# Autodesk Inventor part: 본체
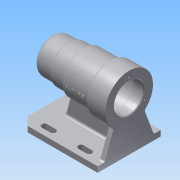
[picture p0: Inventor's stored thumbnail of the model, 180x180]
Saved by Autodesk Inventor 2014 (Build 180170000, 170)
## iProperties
Created: 2017-09
Part Number: 본체
Material: 알루미늄 6061
Document SubType Name: Modeling
Designer: net
Density: 2.71 g/cm^3
Appearance: 알루미늄 - 평지
Mass: 694.456 g
Surface Area: 712.516 cm^2
Volume: 256.257 cm^3
Author: net
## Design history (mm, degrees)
sketch "스케치1"
  geometry: L1 (56, 0)-(-56, 0); L2 (56, 0)-(56, 25); L3 (56, 25)-(31, 25); L4 (31, 25)-(31, 27); L5 (31, 27)-(11, 27); L6 (11, 27)-(11, 30); L7 (11, 30)-(-28, 30); L8 (-28, 30)-(-28, 34); L9 (-28, 34)-(-56, 34); L10 (-56, 21)-(-41, 21); L11 (-41, 21)-(-41, 21); L12 (-38, 24)-(10, 24); L13 (13, 21)-(13, 21); L14 (13, 21)-(24.7, 21); L15 (25, 20.7)-(25, 17.5); L16 (25, 17.5)-(42.7, 17.5); L17 (43, 17.2)-(43, 16); L18 (43, 16)-(46.7, 16); L19 (47, 15.7)-(47, 10.5); L20 (47, 10.5)-(47, 10.5); L21 (50, 7.5)-(50, 0); L22 (-56, 34)-(-56, 21); A1 r 0.3 centre (46.7, 15.7) between (47, 15.7) and (46.7, 16); A2 r 0.3 centre (42.7, 17.2) between (43, 17.2) and (42.7, 17.5); A3 r 3 centre (-38, 21) between (-38, 24) and (-41, 21); A4 r 3 centre (10, 21) between (13, 21) and (10, 24); A5 r 0.3 centre (24.7, 20.7) between (25, 20.7) and (24.7, 21); A6 r 3 centre (47, 7.5) between (50, 7.5) and (47, 10.5); 8 further points
  constraints: 44 end point, 15 point on line, 12 point on circle, 12 tangent, 10 parallel, 10 perpendicular, 6 centre point, 2 equal radius, 1 coincident, 1 horizontal, 1 midpoint
  dimensions: "d0" = 112 distance of L1.start L1.end; "d1" = 25 distance of L2.end L3.end; "d2" = 45 horizontal distance of L5.end L2.end; "d3" = 84 horizontal distance of L7.end L2.end; "d4" = 50 diameter of L2.end L1; "d5" = 54 diameter of L5 L1; "d6" = 60 diameter of L7 L1; "d7" = 68 diameter of L9 L1; "d11" = 15 distance of L10.start L10.end; "d12" = 54 distance of point (-41, 24) point (13, 24); "d13" = 12 distance of L13.end point (25, 21); "d14" = 18 distance of L15.end point (43, 17.5); "d15" = 4 distance of L17.end point (47, 16); "d16" = 3 distance of L19.end point (50, 10.5); "d17" = 48 diameter of L12 L1; "d18" = 42 diameter of L14 L1; "d19" = 21 diameter of L20 L1; "d20" = 32 diameter of L18 L1; "d21" = 35 diameter of L16 L1; "d22" = 42 diameter of L10 L1; "d23" = 112 horizontal distance of L9.end L2.end; "d66" = 3 radius of A3; "d77" = 0.3 radius of A5; "d80" = 0.3 radius of A2; "d81" = 3 radius of A6
revolve "회전1" sketch "스케치1" stored, may be unused: angle "d8" = 90 deg
sketch "스케치2"
  geometry: 1 further point
node "작업 평면1"
sketch "스케치3"
  geometry: L1 (-56, 25)-(-56, -25) reference; L2 (56, 34)-(56, -34) reference; L3 (-56, 45)-(56, 45); L4 (56, 45)-(56, -45); L5 (56, -45)-(-56, -45); L6 (-56, -45)-(-56, 45); 2 further points
  constraints: 8 end point, 2 midpoint, 2 parallel, 1 horizontal, 1 perpendicular
  dimensions: "d25" = 112 distance of L3.start L3.end; "d26" = 90 distance of L5.end L3.start
extrude "돌출1" join sketch "스케치3" distance "d27" = 8; taper "d28" = 0 deg
chamfer "모따기1" distance "d29" = 12; stored, may be unused: second distance "d30" = 2, angle "d31" = 45 deg
sketch "스케치4"
  geometry: L1 (56, 45)-(-44, 45) reference; L2 (20, 33)-(32, 33); L3 (20, 37)-(32, 37); L4 (32, 29)-(20, 29); A1 r 4 centre (20, 33) between (20, 37) and (20, 29); A2 r 4 centre (32, 33) between (32, 29) and (32, 37); 3 further points
  constraints: 8 end point, 4 point on circle, 4 tangent, 2 centre point, 2 parallel, 1 horizontal alignment, 1 midpoint
  dimensions: "d32" = 12 distance of L2.start L2.end; "d33" = 4 radius of A1; "d35" = 24 horizontal distance of L1.start L3.end
extrude "돌출2" cut sketch "스케치4" distance "d36" = 8; taper "d37" = 0 deg
sketch "스케치5"
  geometry: L1 (56, -45)-(56, 45) reference; L2 (-32, -4)-(56, -4); L3 (56, -4)-(56, 4); L4 (56, 4)-(-32, 4); L5 (-32, 4)-(-32, -4); 3 further points
  constraints: 8 end point, 3 midpoint, 2 parallel, 1 horizontal, 1 horizontal alignment, 1 perpendicular
  dimensions: "d41" = 88 distance of L2.start L2.end; "d42" = 8 distance of L4.end L2.start
extrude "돌출3" join sketch "스케치5" stored distance "d43" = 8; taper "d44" = 0 deg
sketch "스케치6"
  geometry: L1 (-8, 41)-(-36.236, 41) reference; L2 (-8, 0)-(-8, 41) reference; L3 (-8, 49)-(-8, 90) reference; L4 (-8, 49)-(-36.236, 49) reference; L5 (-43.992, 23.1)-(-8, 10); L6 (-43.992, 66.9)-(-8, 80); A1 r 34 centre (-70, 45) between (-36.236, 49) and (-36.236, 41) reference
  constraints: 4 end point, 2 point on circle, 2 point on line, 1 equal length
  dimensions: "d48" = 110 deg angle of L2 L5; "d50" = 110 deg angle of L3 L6; "d51" = 10 distance of L2.start L5.end
extrude "돌출4" join sketch "스케치6" distance "d52" = 8; taper "d53" = 0 deg
sketch "스케치7" dims "d54" = 52
  geometry: C1 r 21 at (-70, 45) reference; A1 r 34 centre (-70, 45) between (-43.992, 66.9) and (-43.992, 23.1) reference; 2 further points
  constraints: 2 horizontal alignment, 1 coincident, 2 other
hole "구멍1" sketch "스케치7" at (-96, 45) diameter "d55" = 3.242; stored, may be unused: countersink angle "d59" = 90 deg, drill point angle "d61" = 118 deg; dims "d56" = 8, "d57" = 4, "d58" = 2, "d60" = 11
chamfer "모따기2" distance "d67" = 1; stored, may be unused: second distance "d68" = 2, angle "d69" = 45 deg
fillet "모깎기1" dims "d70" = 3
sketch "스케치9"
  geometry: L1 (3.828, 35.298)-(21, 35.298) reference; L2 (0, 37.322)-(1, 37.322) reference; L3 (0, 0)-(0, 37.322) reference; L4 (88, 35.992)-(88, 0) reference; L5 (0, 0)-(9.458, 35.298); L6 (-12, 0)-(88, 0) reference; 1 further point
  constraints: 2 end point, 1 point on line, 1 other
  dimensions: "d71" = 105 deg angle of L6 L5
extrude "돌출5" cut sketch "스케치9" distance "d72" = 8; taper "d73" = 0 deg
fillet "모깎기2" dims "d74" = 3
fillet "모깎기3" dims "d75" = 3
fillet "모깎기4" dims "d76" = 3
sketch "스케치10"
  geometry: 1 further point
fillet "모깎기5" dims "d82" = 8
sketch "스케치11"
  geometry: 1 further point
node "작업 평면2"
sketch "스케치12"
  geometry: L1 (-27.5, 1.94)-(28.341, 1.94); L2 (28.341, 1.94)-(28.341, -2); L3 (28.341, -2)-(-27.5, -2); L4 (-27.5, -2)-(-27.5, 1.94); L5 (-47.5, -24.711)-(-47.5, 34) reference; L6 (52.5, -70)-(-47.5, -70) reference; 1 further point
  constraints: 2 other
  dimensions: "d84" = 68 distance between parallel lines of L6 L3; "d85" = 20 distance from line of L5 L1.start
feature "엠보싱1" sketch "스케치12" dims "d15" = 4, "d86" = 0.5, "d87" = 0
node "솔리드1"
pattern_linear "직사각형 패턴1" dims "d40" = 52
mirror "대칭1"
pattern_circular "원형 패턴1" dims angle "d63" = 360 deg
